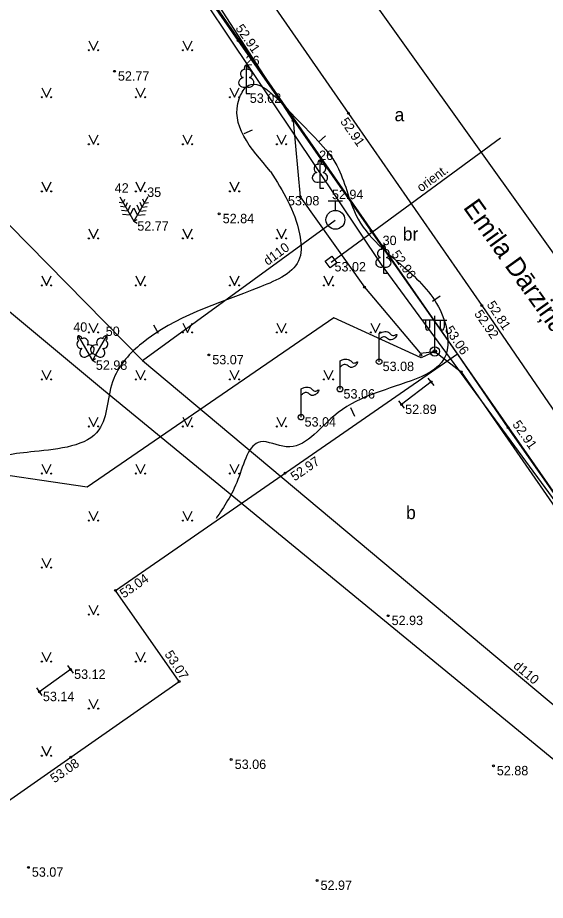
# Model space of a CAD drawing. Extents: x 619806 to 620082, y 405176 to 405386.
# Drawn here: x 619968.46 to 619996.52, y 405292.31 to 405339.23 of the extents above; entities that cross this region are included whole.
import ezdxf

# ---------------------------------------------------------------- set-up
doc = ezdxf.new("R2010")
doc.units = 0
for name, color, linetype in [('APGR_SARK_####_####_#', 7, 'Continuous'), ('APGS_ELEM_####_####_#', 7, 'Continuous'), ('APGS_VADP_ZSPR_####_#', 7, 'Continuous'), ('APGS_VADP_ZSPR_####_I', 7, 'Continuous'), ('BUVE_ELEM_####_####_#', 7, 'Continuous'), ('BUVE_SOLS_####_####_#', 7, 'Continuous'), ('CELI_CAPM_####_####_#', 7, 'Continuous'), ('CELI_CMAL_####_####_#', 7, 'Continuous'), ('CELI_CSEG_####_TKST_#', 7, 'Continuous'), ('CELI_IELA_####_TKST_#', 7, 'Continuous'), ('CELI_SEGL_####_####_#', 7, 'Continuous'), ('ELEK_ELEM_####_####_#', 7, 'Continuous'), ('ELEK_VADP_ZSPR_####_#', 7, 'Continuous'), ('ELEK_VADP_ZSPR_TKST_#', 7, 'Continuous'), ('RAMI_UZMR_####_####_#', 7, 'Continuous'), ('RELJ_AATZ_####_TKST_#', 7, 'Continuous'), ('RELJ_ELEM_####_####_#', 7, 'Continuous'), ('RELJ_HORZ_PAMT_####_#', 7, 'Continuous'), ('ROBZ_UZMR_####_####_#', 7, 'Continuous'), ('SAKT_VADP_KABE_####_#', 7, 'Continuous'), ('TERT_DIAM_####_TKST_#', 7, 'Continuous'), ('TERT_ELEM_####_####_#', 7, 'Continuous'), ('UDTK_ELEM_####_####_#', 7, 'Continuous'), ('UDTK_ELEM_####_TKST_#', 7, 'Continuous'), ('UDTK_VADP_UDEN_####_#', 7, 'Continuous'), ('UDTK_VADP_UDEN_TKST_#', 7, 'Continuous')]:
    doc.layers.add(name, color=color, linetype=linetype)

msp = doc.modelspace()

# ---------------------------------------------------------------- linework, layer by layer
at = {"layer": 'APGR_SARK_####_####_#'}
msp.add_lwpolyline([(619976.198, 405343.424), (619987.786, 405326.116), (620001.138, 405307.928), (620014.265, 405290.061), (620015.405, 405288.784), (620016.767, 405287.746), (620041.487, 405272.379), (619990.053, 405197.403), (619990.053, 405197.403)], dxfattribs=at)
at = {"layer": 'APGS_ELEM_####_####_#'}
for p, q in [((619990.647, 405323.159), (619990.012, 405323.154)), ((619990.147, 405323.155), (619990.147, 405322.763)), ((619990.357, 405323.157), (619990.357, 405322.763)), ((619990.647, 405321.492), (619990.647, 405323.375)), ((619990.647, 405323.159), (619991.282, 405323.154)), ((619990.937, 405323.157), (619990.937, 405322.763)), ((619991.147, 405323.155), (619991.147, 405322.763))]:
    msp.add_line(p, q, dxfattribs=at)
for radius in [0.25, 0.09, 0.0225]:
    msp.add_circle((619990.647, 405321.492), radius, dxfattribs=at)
for centre, major_axis, start_param, end_param in [((619990.252, 405322.763), (0, 0.151), 1.570796, 4.712389), ((619991.042, 405322.763), (0, -0.151), 4.712389, 7.853982)]:
    msp.add_ellipse(centre, major_axis=major_axis, ratio=0.695971, start_param=start_param, end_param=end_param, dxfattribs=at)
at = {"layer": 'APGS_VADP_ZSPR_####_#'}
for points in [[(619961.504, 405361.726), (619962.514, 405361.45), (619963.297, 405361.02), (619965.532, 405357.753), (619972.641, 405348.158), (619978.792, 405340.446), (619983.119, 405333.754), (619983.491, 405329.711), (619986.9, 405324.905), (619989.872, 405321.397), (619990.647, 405321.492)], [(619990.647, 405321.492), (619992.044, 405320.41), (619998.442, 405311.177), (620006.316, 405300.184), (620012.827, 405290.604), (620013.926, 405290.046), (620013.66, 405289.472), (620014.139, 405289.916), (620020.167, 405285.36), (620029.979, 405279.119), (620034.093, 405276.637), (620034.718, 405277.157), (620034.581, 405276.433), (620041.718, 405272.423), (620046.265, 405269.109)]]:
    msp.add_lwpolyline(points, dxfattribs=at)
at = {"layer": 'APGS_VADP_ZSPR_####_I'}
msp.add_lwpolyline([(619990.647, 405321.492), (619989.924, 405321.154), (619985.279, 405323.283), (619972.163, 405314.266), (619965.642, 405315.238)], dxfattribs=at)
at = {"layer": 'BUVE_ELEM_####_####_#'}
for p, q in [((619987.685, 405322.108), (619987.685, 405322.445)), ((619987.685, 405320.945), (619987.685, 405322.108)), ((619985.606, 405320.647), (619985.606, 405320.984)), ((619985.606, 405319.484), (619985.606, 405320.647)), ((619983.537, 405319.157), (619983.537, 405319.494)), ((619983.537, 405317.994), (619983.537, 405319.157))]:
    msp.add_line(p, q, dxfattribs=at)
for centre in [(619987.685, 405320.945), (619985.606, 405319.484), (619983.537, 405317.994)]:
    msp.add_circle(centre, 0.148, dxfattribs=at)
for points in [[(619987.685, 405322.445), (619987.847, 405322.519), (619988.123, 405322.528), (619988.229, 405322.475), (619988.366, 405322.348), (619988.471, 405322.336), (619988.621, 405322.393), (619988.535, 405322.221), (619988.398, 405322.126), (619988.246, 405322.105), (619988.07, 405322.221), (619987.858, 405322.247), (619987.79, 405322.206), (619987.685, 405322.108)], [(619985.606, 405320.984), (619985.768, 405321.058), (619986.044, 405321.067), (619986.15, 405321.014), (619986.287, 405320.887), (619986.392, 405320.875), (619986.542, 405320.932), (619986.456, 405320.76), (619986.319, 405320.665), (619986.167, 405320.644), (619985.991, 405320.76), (619985.779, 405320.786), (619985.711, 405320.745), (619985.606, 405320.647)], [(619983.537, 405319.494), (619983.699, 405319.568), (619983.975, 405319.577), (619984.081, 405319.524), (619984.218, 405319.397), (619984.323, 405319.385), (619984.473, 405319.442), (619984.387, 405319.27), (619984.25, 405319.175), (619984.098, 405319.154), (619983.922, 405319.27), (619983.71, 405319.296), (619983.642, 405319.255), (619983.537, 405319.157)]]:
    msp.add_spline(points, degree=3, dxfattribs=at)
at = {"layer": 'BUVE_SOLS_####_####_#'}
for p, q in [((619990.453, 405319.871), (619988.884, 405318.665)), ((619990.605, 405319.673), (619990.301, 405320.069)), ((619989.036, 405318.467), (619988.732, 405318.863)), ((619971.428, 405304.378), (619971.138, 405304.786)), ((619971.283, 405304.582), (619969.622, 405303.398)), ((619969.767, 405303.194), (619969.477, 405303.602))]:
    msp.add_line(p, q, dxfattribs=at)
at = {"layer": 'CELI_CAPM_####_####_#'}
msp.add_lwpolyline([(619965.216, 405366.112), (619969.788, 405359.459), (619973.297, 405354.436), (619974.566, 405352.6), (619974.617, 405350.85), (619979.181, 405344.059), (619986.049, 405334.146), (619993.139, 405323.923), (619997.124, 405318.139), (620003.902, 405308.323), (620010.301, 405299.151), (620015.066, 405292.395), (620017.489, 405291.013)], dxfattribs=at)
at = {"layer": 'CELI_CMAL_####_####_#'}
for points in [[(619991.854, 405321.355), (619987.265, 405327.894), (619980.195, 405338.024), (619973.089, 405348.264), (619967.033, 405357.029), (619962.383, 405363.658), (619953.25, 405359.322), (619947.967, 405356.794), (619934.832, 405350.507), (619928.431, 405340.813), (619925.67, 405336.505), (619926.565, 405335.935), (619923.8, 405331.651)], [(619951.468, 405293.381), (619960.885, 405299.892), (619964.19, 405294.965), (619971.285, 405299.927), (619977.055, 405303.943), (619973.673, 405308.787), (619991.854, 405321.355)]]:
    msp.add_lwpolyline(points, dxfattribs=at)
at = {"layer": 'CELI_SEGL_####_####_#'}
msp.add_lwpolyline([(620013.524, 405289.938), (620008.624, 405297.164), (620001.476, 405307.535), (619994.548, 405317.437), (619991.854, 405321.355)], dxfattribs=at)
at = {"layer": 'ELEK_ELEM_####_####_#'}
msp.add_lwpolyline([(619985.084, 405325.931), (619984.817, 405326.29), (619985.17, 405326.553), (619985.437, 405326.194)], close=True, dxfattribs=at)
at = {"layer": 'ELEK_VADP_ZSPR_####_#'}
msp.add_lwpolyline([(619985.127, 405326.242), (619994.138, 405332.845)], dxfattribs=at)
at = {"layer": 'RAMI_UZMR_####_####_#'}
msp.add_lwpolyline([(619874.687, 405324.979), (619926.719, 405349.544), (619966.669, 405369.042), (620021.738, 405292.03), (620049.703, 405275.476), (620026.189, 405242.287), (620012.147, 405222.917), (619996.603, 405200.928), (619989.997, 405199.173), (619982.328, 405199.155), (619922.669, 405233.014), (619882.137, 405255.756), (619859.084, 405268.056), (619820.646, 405290.715), (619813.744, 405295.206), (619820.645, 405298.752)], close=True, dxfattribs=at)
at = {"layer": 'RELJ_ELEM_####_####_#'}
for centre in [(619980.195, 405338.024), (619973.61, 405336.382), (619986.049, 405334.146), (619983.119, 405333.754), (619983.491, 405329.711), (619979.182, 405328.805), (619987.265, 405327.894), (619986.9, 405324.905), (619993.139, 405323.923), (619978.63, 405321.303), (619989.9, 405321.292), (619992.044, 405320.41), (619990.453, 405319.871), (619988.884, 405318.665), (619994.548, 405317.437), (619982.681, 405315.014), (619973.673, 405308.787), (619988.164, 405307.443), (619971.283, 405304.582), (619977.055, 405303.943), (619969.622, 405303.398), (619971.285, 405299.927), (619979.82, 405299.794), (619993.759, 405299.457), (619969.034, 405294.065), (619984.385, 405293.363)]:
    msp.add_circle(centre, 0.05, dxfattribs=at)
at = {"layer": 'RELJ_HORZ_PAMT_####_#'}
for p, q in [((619980.501, 405333.079), (619980.96, 405333.277)), ((619984.833, 405332.948), (619984.455, 405332.621)), ((619990.933, 405324.422), (619990.519, 405324.141)), ((619975.69, 405322.896), (619975.935, 405322.46)), ((619986.396, 405318.031), (619986.189, 405318.486))]:
    msp.add_line(p, q, dxfattribs=at)
for points in [[(619981.917, 405331.06), (619980.248, 405334.925), (619980.623, 405335.551), (619983.208, 405333.945), (619985.525, 405331.192), (619986.573, 405328.521), (619989.402, 405325.613), (619991.147, 405323.155), (619991.147, 405321.111), (619989.385, 405319.934), (619985.271, 405318.053), (619982.748, 405316.419), (619981.371, 405316.685), (619980.179, 405314.685), (619979.015, 405312.611)], [(619981.917, 405331.06), (619983.458, 405327.733), (619983.458, 405326.44), (619981.371, 405324.921), (619975.066, 405321.914), (619973.572, 405320.043), (619972.785, 405317.322), (619969.353, 405316.166), (619966.558, 405315.51), (619964.797, 405313.519), (619963.449, 405310.459), (619961.207, 405309.682), (619957.576, 405309.593), (619955.503, 405308.248), (619954.267, 405303.638), (619953.77, 405299.801), (619953.847, 405298.296), (619954.537, 405297.798), (619956.258, 405297.458), (619956.781, 405297.091)]]:
    msp.add_spline(points, degree=3, dxfattribs=at)
at = {"layer": 'ROBZ_UZMR_####_####_#'}
for p, q in [((619962.326, 405363.803), (619991.921, 405321.247)), ((619991.921, 405321.247), (620012.847, 405291.155))]:
    msp.add_line(p, q, dxfattribs=at)
at = {"layer": 'SAKT_VADP_KABE_####_#'}
msp.add_lwpolyline([(619935.629, 405357.201), (619939.538, 405347.363), (619973.032, 405319.457), (620006.975, 405291.595), (620036.262, 405267.248), (620043.553, 405261.241)], dxfattribs=at)
at = {"layer": 'TERT_ELEM_####_####_#'}
for p, q in [((619972.25, 405338), (619972.5, 405337.5)), ((619972.5, 405337.5), (619972.75, 405338)), ((619977.25, 405338), (619977.5, 405337.5)), ((619977.5, 405337.5), (619977.75, 405338)), ((619969.75, 405335.5), (619970, 405335)), ((619970, 405335), (619970.25, 405335.5)), ((619974.75, 405335.5), (619975, 405335)), ((619975, 405335), (619975.25, 405335.5)), ((619979.75, 405335.5), (619980, 405335)), ((619980, 405335), (619980.25, 405335.5)), ((619980.623, 405335.551), (619980.623, 405335.204)), ((619980.623, 405335.204), (619980.823, 405335.204)), ((619972.25, 405333), (619972.5, 405332.5)), ((619972.5, 405332.5), (619972.75, 405333)), ((619977.25, 405333), (619977.5, 405332.5)), ((619977.5, 405332.5), (619977.75, 405333)), ((619982.25, 405333), (619982.5, 405332.5)), ((619982.5, 405332.5), (619982.75, 405333)), ((619969.75, 405330.5), (619970, 405330)), ((619970, 405330), (619970.25, 405330.5)), ((619974.75, 405330.5), (619975, 405330)), ((619975, 405330), (619975.25, 405330.5)), ((619979.75, 405330.5), (619980, 405330)), ((619980, 405330), (619980.25, 405330.5)), ((619984.537, 405330.513), (619984.537, 405330.166)), ((619984.537, 405330.166), (619984.737, 405330.166)), ((619973.892, 405329.706), (619974.642, 405328.407)), ((619975.392, 405329.706), (619974.642, 405328.407)), ((619974.08, 405329.38), (619973.864, 405329.403)), ((619974.205, 405329.164), (619973.939, 405329.193)), ((619974.08, 405329.38), (619974.167, 405329.578)), ((619974.205, 405329.164), (619974.313, 405329.409)), ((619974.33, 405328.947), (619974.469, 405329.263)), ((619974.954, 405328.947), (619974.815, 405329.263)), ((619975.079, 405329.164), (619974.971, 405329.409)), ((619975.079, 405329.164), (619975.345, 405329.193)), ((619975.204, 405329.38), (619975.116, 405329.579)), ((619975.204, 405329.38), (619975.419, 405329.404)), ((619974.33, 405328.947), (619973.987, 405328.985)), ((619974.455, 405328.731), (619974.045, 405328.776)), ((619974.455, 405328.731), (619974.622, 405329.109)), ((619974.829, 405328.731), (619974.663, 405329.108)), ((619974.829, 405328.731), (619975.24, 405328.775)), ((619974.954, 405328.947), (619975.297, 405328.985)), ((619974.642, 405328.407), (619974.815, 405328.507)), ((619974.642, 405328.407), (619974.815, 405328.307)), ((619972.25, 405328), (619972.5, 405327.5)), ((619972.5, 405327.5), (619972.75, 405328)), ((619977.25, 405328), (619977.5, 405327.5)), ((619977.5, 405327.5), (619977.75, 405328)), ((619982.25, 405328), (619982.5, 405327.5)), ((619982.5, 405327.5), (619982.75, 405328)), ((619987.912, 405325.99), (619987.912, 405325.643)), ((619969.75, 405325.5), (619970, 405325)), ((619970, 405325), (619970.25, 405325.5)), ((619974.75, 405325.5), (619975, 405325)), ((619975, 405325), (619975.25, 405325.5)), ((619979.75, 405325.5), (619980, 405325)), ((619980, 405325), (619980.25, 405325.5)), ((619984.75, 405325.5), (619985, 405325)), ((619985, 405325), (619985.25, 405325.5)), ((619987.912, 405325.643), (619988.112, 405325.643)), ((619972.25, 405323), (619972.5, 405322.5)), ((619972.5, 405322.5), (619972.75, 405323)), ((619977.25, 405323), (619977.5, 405322.5)), ((619977.5, 405322.5), (619977.75, 405323)), ((619982.25, 405323), (619982.5, 405322.5)), ((619982.5, 405322.5), (619982.75, 405323)), ((619987.25, 405323), (619987.5, 405322.5)), ((619987.5, 405322.5), (619987.75, 405323)), ((619972.264, 405321.314), (619972.437, 405321.013)), ((619972.61, 405321.314), (619972.437, 405321.013)), ((619972.437, 405321.013), (619972.61, 405321.113)), ((619972.437, 405321.013), (619972.61, 405320.913)), ((619969.75, 405320.5), (619970, 405320)), ((619970, 405320), (619970.25, 405320.5)), ((619974.75, 405320.5), (619975, 405320)), ((619975, 405320), (619975.25, 405320.5)), ((619979.75, 405320.5), (619980, 405320)), ((619980, 405320), (619980.25, 405320.5)), ((619984.75, 405320.5), (619985, 405320)), ((619985, 405320), (619985.25, 405320.5)), ((619972.25, 405318), (619972.5, 405317.5)), ((619972.5, 405317.5), (619972.75, 405318)), ((619977.25, 405318), (619977.5, 405317.5)), ((619977.5, 405317.5), (619977.75, 405318)), ((619982.25, 405318), (619982.5, 405317.5)), ((619982.5, 405317.5), (619982.75, 405318)), ((619969.75, 405315.5), (619970, 405315)), ((619970, 405315), (619970.25, 405315.5)), ((619974.75, 405315.5), (619975, 405315)), ((619975, 405315), (619975.25, 405315.5)), ((619979.75, 405315.5), (619980, 405315)), ((619980, 405315), (619980.25, 405315.5)), ((619972.25, 405313), (619972.5, 405312.5)), ((619972.5, 405312.5), (619972.75, 405313)), ((619977.25, 405313), (619977.5, 405312.5)), ((619977.5, 405312.5), (619977.75, 405313)), ((619969.75, 405310.5), (619970, 405310)), ((619970, 405310), (619970.25, 405310.5)), ((619972.25, 405308), (619972.5, 405307.5)), ((619972.5, 405307.5), (619972.75, 405308)), ((619969.75, 405305.5), (619970, 405305)), ((619970, 405305), (619970.25, 405305.5)), ((619974.75, 405305.5), (619975, 405305)), ((619975, 405305), (619975.25, 405305.5)), ((619972.25, 405303), (619972.5, 405302.5)), ((619972.5, 405302.5), (619972.75, 405303)), ((619969.75, 405300.5), (619970, 405300)), ((619970, 405300), (619970.25, 405300.5))]:
    msp.add_line(p, q, dxfattribs=at)
for points in [[(619980.623, 405336.704), (619980.623, 405335.551)], [(619980.713, 405336.472), (619980.712, 405336.473)], [(619984.537, 405331.666), (619984.537, 405330.513)], [(619984.627, 405331.434), (619984.626, 405331.435)], [(619987.912, 405327.143), (619987.912, 405325.99)], [(619988.002, 405326.911), (619988.001, 405326.912)], [(619971.687, 405322.312), (619972.264, 405321.314)], [(619971.881, 405322.156), (619971.879, 405322.156)], [(619973.187, 405322.312), (619972.61, 405321.314)], [(619973.148, 405322.066), (619973.148, 405322.067)]]:
    msp.add_lwpolyline(points, dxfattribs=at)
for centre, radius in [((619972.25, 405337.5), 0.028), ((619972.75, 405337.5), 0.0263), ((619977.25, 405337.5), 0.028), ((619977.75, 405337.5), 0.0263), ((619969.75, 405335), 0.028), ((619970.25, 405335), 0.0263), ((619974.75, 405335), 0.028), ((619975.25, 405335), 0.0263), ((619979.75, 405335), 0.028), ((619980.25, 405335), 0.0263), ((619972.25, 405332.5), 0.028), ((619972.75, 405332.5), 0.0263), ((619977.25, 405332.5), 0.028), ((619977.75, 405332.5), 0.0263), ((619982.25, 405332.5), 0.028), ((619982.75, 405332.5), 0.0263), ((619969.75, 405330), 0.028), ((619970.25, 405330), 0.0263), ((619974.75, 405330), 0.028), ((619975.25, 405330), 0.0263), ((619979.75, 405330), 0.028), ((619980.25, 405330), 0.0263), ((619972.25, 405327.5), 0.028), ((619972.75, 405327.5), 0.0263), ((619977.25, 405327.5), 0.028), ((619977.75, 405327.5), 0.0263), ((619982.25, 405327.5), 0.028), ((619982.75, 405327.5), 0.0263), ((619969.75, 405325), 0.028), ((619970.25, 405325), 0.0263), ((619974.75, 405325), 0.028), ((619975.25, 405325), 0.0263), ((619979.75, 405325), 0.028), ((619980.25, 405325), 0.0263), ((619984.75, 405325), 0.028), ((619985.25, 405325), 0.0263), ((619972.25, 405322.5), 0.028), ((619972.75, 405322.5), 0.0263), ((619977.25, 405322.5), 0.028), ((619977.75, 405322.5), 0.0263), ((619982.25, 405322.5), 0.028), ((619982.75, 405322.5), 0.0263), ((619987.25, 405322.5), 0.028), ((619987.75, 405322.5), 0.0263), ((619969.75, 405320), 0.028), ((619970.25, 405320), 0.0263), ((619974.75, 405320), 0.028), ((619975.25, 405320), 0.0263), ((619979.75, 405320), 0.028), ((619980.25, 405320), 0.0263), ((619984.75, 405320), 0.028), ((619985.25, 405320), 0.0263), ((619972.25, 405317.5), 0.028), ((619972.75, 405317.5), 0.0263), ((619977.25, 405317.5), 0.028), ((619977.75, 405317.5), 0.0263), ((619982.25, 405317.5), 0.028), ((619982.75, 405317.5), 0.0263), ((619969.75, 405315), 0.028), ((619970.25, 405315), 0.0263), ((619974.75, 405315), 0.028), ((619975.25, 405315), 0.0263), ((619979.75, 405315), 0.028), ((619980.25, 405315), 0.0263), ((619972.25, 405312.5), 0.028), ((619972.75, 405312.5), 0.0263), ((619977.25, 405312.5), 0.028), ((619977.75, 405312.5), 0.0263), ((619969.75, 405310), 0.028), ((619970.25, 405310), 0.0263), ((619972.25, 405307.5), 0.028), ((619972.75, 405307.5), 0.0263), ((619969.75, 405305), 0.028), ((619970.25, 405305), 0.0263), ((619974.75, 405305), 0.028), ((619975.25, 405305), 0.0263), ((619972.25, 405302.5), 0.028), ((619972.75, 405302.5), 0.0263), ((619969.75, 405300), 0.028), ((619970.25, 405300), 0.0263)]:
    msp.add_circle(centre, radius, dxfattribs=at)
for centre, major_axis, ratio, start_param, end_param in [((619980.623, 405336.554), (0, -0.15), 0.707107, 3.14537, 5.287485), ((619980.623, 405336.554), (0, -0.15), 0.707107, 0.995701, 3.137816), ((619980.495, 405336.259), (-0.039, -0.212), 0.861323, 3.141593, 6.283185), ((619980.751, 405336.259), (0.039, -0.212), 0.861323, 0, 3.141593), ((619980.533, 405335.797), (0.307, 0.095), 0.814445, 1.570796, 4.752015), ((619980.713, 405335.797), (-0.307, 0.095), 0.814445, 1.531171, 4.712389), ((619984.537, 405331.516), (0, -0.15), 0.707107, 3.14537, 5.287485), ((619984.537, 405331.516), (0, -0.15), 0.707107, 0.995701, 3.137816), ((619984.409, 405331.221), (-0.039, -0.212), 0.861323, 3.141593, 6.283185), ((619984.665, 405331.221), (0.039, -0.212), 0.861323, 0, 3.141593), ((619984.447, 405330.759), (0.307, 0.095), 0.814445, 1.570796, 4.752015), ((619984.627, 405330.759), (-0.307, 0.095), 0.814445, 1.531171, 4.712389), ((619987.784, 405326.698), (-0.039, -0.212), 0.861323, 3.141593, 6.283185), ((619987.912, 405326.993), (0, -0.15), 0.707107, 3.14537, 5.287485), ((619987.912, 405326.993), (0, -0.15), 0.707107, 0.995701, 3.137816), ((619988.04, 405326.698), (0.039, -0.212), 0.861323, 0, 3.141593), ((619987.822, 405326.236), (0.307, 0.095), 0.814445, 1.570796, 4.752015), ((619988.002, 405326.236), (-0.307, 0.095), 0.814445, 1.531171, 4.712389), ((619971.762, 405322.182), (0.075, -0.13), 0.707107, 3.14537, 5.287485), ((619971.762, 405322.182), (0.075, -0.13), 0.707107, 0.995701, 3.137816), ((619972.021, 405321.991), (0.14, -0.165), 0.861323, 0, 3.141593), ((619972.853, 405321.991), (-0.14, -0.165), 0.861323, 3.141593, 6.283185), ((619973.112, 405322.182), (-0.075, -0.13), 0.707107, 3.14537, 5.287485), ((619973.112, 405322.182), (-0.075, -0.13), 0.707107, 0.995701, 3.137816), ((619971.798, 405321.863), (0.073, -0.203), 0.861323, 3.141593, 6.283185), ((619972.218, 405321.571), (-0.313, -0.071), 0.814445, 1.531171, 4.712389), ((619972.656, 405321.571), (0.313, -0.071), 0.814445, 1.570796, 4.752015), ((619973.076, 405321.863), (-0.073, -0.203), 0.861323, 0, 3.141593), ((619972.063, 405321.482), (0.218, 0.236), 0.814445, 1.570796, 4.752015), ((619972.811, 405321.482), (-0.218, 0.236), 0.814445, 1.531171, 4.712389)]:
    msp.add_ellipse(centre, major_axis=major_axis, ratio=ratio, start_param=start_param, end_param=end_param, dxfattribs=at)
at = {"layer": 'UDTK_ELEM_####_####_#'}
for p, q in [((619984.984, 405329.488), (619985.734, 405329.488)), ((619985.359, 405328.988), (619985.359, 405329.488))]:
    msp.add_line(p, q, dxfattribs=at)
msp.add_circle((619985.359, 405328.488), 0.5, dxfattribs=at)
at = {"layer": 'UDTK_VADP_UDEN_####_#'}
for points in [[(619945.834, 405355.555), (619951.504, 405344.209), (619959.966, 405336.395), (619975.103, 405321.007), (620000.001, 405300.143)], [(619975.103, 405321.007), (619985.357, 405328.467)]]:
    msp.add_lwpolyline(points, dxfattribs=at)

# ---------------------------------------------------------------- texts
at = {"layer": 'CELI_CSEG_####_TKST_#'}
for s, p in [('a', (619988.505, 405333.726)), ('br', (619988.941, 405327.385)), ('b', (619989.117, 405312.576))]:
    msp.add_text(s, height=0.7, dxfattribs=at).set_placement(p)
at = {"layer": 'CELI_IELA_####_TKST_#'}
msp.add_text('Emīla Dārziņa iela', height=1, rotation=305.5671, dxfattribs=at).set_placement((619992.123, 405329.138))
at = {"layer": 'ELEK_VADP_ZSPR_TKST_#'}
msp.add_text('orient.', height=0.5, rotation=36.2347, dxfattribs=at).set_placement((619989.916, 405329.938))
at = {"layer": 'RELJ_AATZ_####_TKST_#'}
for s, rotation, p in [(' 52.91', 304.9122, (619979.918, 405338.822)), (' 52.91', 304.7426, (619985.491, 405333.861)), (' 52.96', 305.0646, (619988.209, 405326.807)), (' 52.81', 303.076, (619993.285, 405324.132)), (' 52.92', 304.5657, (619992.617, 405323.639)), (' 53.06', 303.5987, (619991.055, 405322.802)), (' 52.91', 304.9788, (619994.642, 405317.761)), (' 52.97', 34.6551, (619983.046, 405314.47)), (' 53.04', 34.6551, (619973.957, 405308.243)), (' 53.07', 302.7876, (619976.156, 405305.552)), (' 53.08', 34.8385, (619970.268, 405298.418))]:
    msp.add_text(s, height=0.5, rotation=rotation, dxfattribs=at).set_placement(p)
for s, p in [(' 52.77', (619973.61, 405335.882)), (' 53.02', (619980.623, 405334.704)), (' 53.08', (619982.65, 405329.253)), (' 52.84', (619979.182, 405328.305)), (' 52.77', (619974.642, 405327.907)), (' 53.02', (619985.127, 405325.742)), (' 53.07', (619978.63, 405320.803)), (' 52.98', (619972.437, 405320.513)), (' 53.08', (619987.685, 405320.445)), (' 53.06', (619985.606, 405318.984)), (' 52.89', (619988.884, 405318.165)), (' 53.04', (619983.537, 405317.494)), (' 52.93', (619988.164, 405306.943)), (' 53.12', (619971.283, 405304.082)), (' 53.14', (619969.622, 405302.898)), (' 53.06', (619979.82, 405299.294)), (' 52.88', (619993.759, 405298.957)), (' 53.07', (619969.034, 405293.565)), (' 52.97', (619984.385, 405292.863))]:
    msp.add_text(s, height=0.5, dxfattribs=at).set_placement(p)
at = {"layer": 'TERT_DIAM_####_TKST_#'}
for s, p in [(' 26', (619980.398, 405336.704)), (' 26', (619984.312, 405331.666)), (' 42', (619973.442, 405329.931)), (' 35', (619975.167, 405329.706)), (' 30', (619987.687, 405327.143)), (' 40', (619971.237, 405322.537)), (' 50', (619972.962, 405322.312))]:
    msp.add_text(s, height=0.5, dxfattribs=at).set_placement(p)
at = {"layer": 'UDTK_ELEM_####_TKST_#'}
msp.add_text('52.94', height=0.5, dxfattribs=at).set_placement((619985.177, 405329.585))
at = {"layer": 'UDTK_VADP_UDEN_TKST_#'}
for rotation, p in [(36.0367, (619981.761, 405326.036)), (320.0377, (619994.784, 405304.71))]:
    msp.add_text('d110', height=0.5, rotation=rotation, dxfattribs=at).set_placement(p)

doc.saveas('drawing.dxf')
